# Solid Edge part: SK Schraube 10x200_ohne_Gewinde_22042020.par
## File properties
Author: Technik
Template: Normal.par
Last saved by: fknapp
Revision: 32
Application: Solid Edge
Username: fknapp
Material: Aluminium
Genauigkeit: 0,99
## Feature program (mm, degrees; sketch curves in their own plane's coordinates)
sketch for "unnamed RevolvedProtrusion 1" plane through (0, 0, 0) normal (0, 0, 1) x-axis (1, 0, 0)
  line (0, 54) -> (9, 54)
  line (9, 54) -> (9, 53)
  line (9, 53) -> (5, 49)
  line (5, 49) -> (5, 46.3)
  line (4.5, 42) -> (5, 46.3)
  line (4.5, -133) -> (4.5, 42)
  line (0.5, -146) -> (4.5, -133)
  line (0, -146) -> (0.5, -146)
revolve "unnamed RevolvedProtrusion 1" add full turn 360 deg about sketch line (0, 54) -> (0, -146)
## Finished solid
Body 1: solid body, 8 faces, 7 edges, 0 vertices.
  Faces by surface: cone 3, cylinder 3, plane 2
  Edges by curve: circle 7
Bounding box of the edges (mm): 18.000 x 200.000 x 18.000, from (-9, -146, -9) to (9, 54, 9).
Cylindrical faces by radius (mm): R4.5 x1, R5 x1, R9 x1
Conical faces (half-angle, radius in mm at the cone's reference point): 6.6325 deg R5 x1, 17.1027 deg R4.5 x1, 45 deg R9 x1
Planar faces by outward normal: +y 1, -y 1
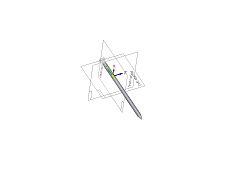
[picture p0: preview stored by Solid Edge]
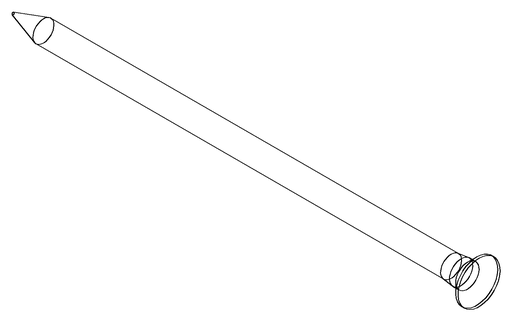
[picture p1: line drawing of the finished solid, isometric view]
